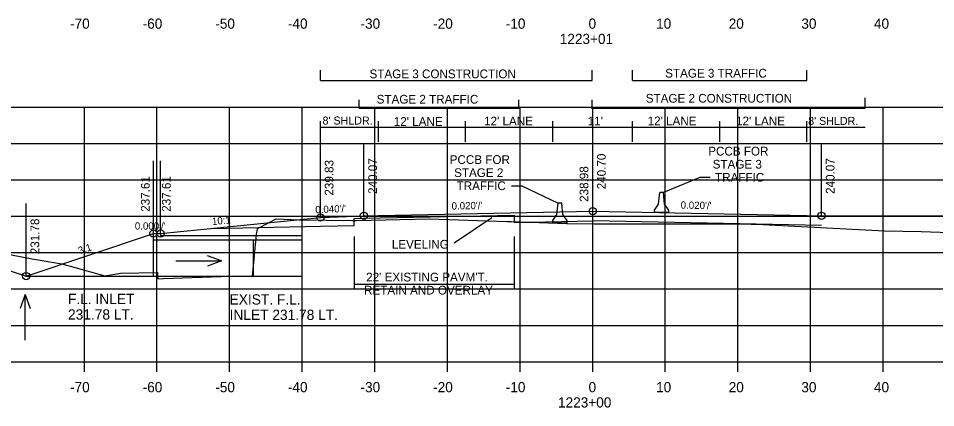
# Model space of a CAD drawing. Extents: x 1342547 to 1344156, y -1532351 to -1517216.
# Drawn here: x 1342623.8 to 1342750.1, y -1531484.1 to -1531430.6 of the extents above; entities that cross this region are included whole.
import ezdxf

# ---------------------------------------------------------------- set-up
doc = ezdxf.new("R2010")
doc.units = 0
for name, color, linetype in [('R_Alt Surface', 7, 'Continuous'), ('R_Axis', 7, 'Continuous'), ('R_Axis Annot', 7, 'Continuous'), ('R_Border Notes', 7, 'Continuous'), ('R_Draft', 7, 'Continuous'), ('R_Drive', 7, 'Continuous'), ('R_Exist Surface', 7, 'Continuous'), ('R_Fin Surface', 7, 'Continuous'), ('R_Grid', 7, 'Continuous'), ('R_MOT', 7, 'Continuous'), ('R_No Plot', 7, 'Continuous'), ('R_Water', 7, 'Continuous'), ('R_Xsect Elev', 7, 'Continuous'), ('R_Xsect Slope', 7, 'Continuous')]:
    doc.layers.add(name, color=color, linetype=linetype)

msp = doc.modelspace()

# ---------------------------------------------------------------- linework, layer by layer
at = {"layer": 'R_Alt Surface'}
for points in [[(1342670.04, -1531459.08), (1342670.04, -1531458.11), (1342671.37, -1531458.06), (1342692.04, -1531457.64)], [(1342692.04, -1531457.64), (1342692.04, -1531458.64), (1342702.87, -1531458.43)], [(1342734.37, -1531459.06), (1342702.87, -1531458.43)], [(1342650.37, -1531459.48), (1342665.37, -1531459.18)], [(1342665.37, -1531459.18), (1342670.04, -1531459.08)]]:
    msp.add_lwpolyline(points, dxfattribs=at)
at = {"layer": 'R_Axis'}
for p, q in [((1342562.87, -1531477.8), (1342842.87, -1531477.8)), ((1342632.87, -1531479.2), (1342632.87, -1531477.8)), ((1342642.87, -1531479.2), (1342642.87, -1531477.8)), ((1342652.87, -1531479.2), (1342652.87, -1531477.8)), ((1342662.87, -1531479.2), (1342662.87, -1531477.8)), ((1342672.87, -1531479.2), (1342672.87, -1531477.8)), ((1342682.87, -1531479.2), (1342682.87, -1531477.8)), ((1342692.87, -1531479.2), (1342692.87, -1531477.8)), ((1342702.87, -1531479.2), (1342702.87, -1531477.8)), ((1342712.87, -1531479.2), (1342712.87, -1531477.8)), ((1342722.87, -1531479.2), (1342722.87, -1531477.8)), ((1342732.87, -1531479.2), (1342732.87, -1531477.8)), ((1342742.87, -1531479.2), (1342742.87, -1531477.8))]:
    msp.add_line(p, q, dxfattribs=at)
at = {"layer": 'R_Draft'}
for p, q in [((1342665.37, -1531439.13), (1342665.37, -1531437.7)), ((1342702.78, -1531439.13), (1342702.78, -1531437.7)), ((1342708.37, -1531439.13), (1342708.37, -1531437.7)), ((1342732.37, -1531439.13), (1342732.37, -1531437.7)), ((1342665.37, -1531439.13), (1342702.78, -1531439.13)), ((1342708.37, -1531439.13), (1342732.37, -1531439.13)), ((1342670.72, -1531442.93), (1342670.72, -1531441.78)), ((1342692.72, -1531443.02), (1342692.72, -1531441.78)), ((1342702.78, -1531443.02), (1342702.78, -1531441.78)), ((1342740.38, -1531442.93), (1342740.38, -1531441.5)), ((1342670.72, -1531442.93), (1342692.72, -1531442.93)), ((1342702.78, -1531442.93), (1342740.38, -1531442.93)), ((1342670.04, -1531460.6), (1342670.04, -1531467.8)), ((1342692.04, -1531460.6), (1342692.04, -1531467.8)), ((1342670.04, -1531467.13), (1342692.04, -1531467.13))]:
    msp.add_line(p, q, dxfattribs=at)
for points in [[(1342717.62, -1531452.45), (1342712.61, -1531454.53)], [(1342719.06, -1531452.45), (1342717.62, -1531452.45)], [(1342691.67, -1531453.62), (1342693.11, -1531453.62)], [(1342693.11, -1531453.62), (1342698.11, -1531455.98)]]:
    msp.add_lwpolyline(points, dxfattribs=at)
at = {"layer": 'R_Drive'}
msp.add_lwpolyline([(1342734.37, -1531457.72), (1342752.37, -1531457.68), (1342842.87, -1531459.71)], dxfattribs=at)
at = {"layer": 'R_Exist Surface'}
msp.add_lwpolyline([(1342615.89, -1531461.76), (1342625.7, -1531463.65), (1342629.76, -1531464.35), (1342635.7, -1531465.98), (1342637.84, -1531465.62), (1342642.95, -1531465.53), (1342643, -1531466.39), (1342643.77, -1531466.37), (1342651.7, -1531466.07), (1342655.92, -1531465.97), (1342655.99, -1531465.98), (1342656.02, -1531465.98), (1342656.26, -1531463.7), (1342656.56, -1531460.23), (1342656.67, -1531459.86), (1342656.72, -1531459.5), (1342658.41, -1531458.62), (1342659.27, -1531458.14), (1342662.46, -1531458.28), (1342662.49, -1531458.28), (1342662.55, -1531458.28), (1342669.78, -1531458.37), (1342670.36, -1531458.36), (1342680.4, -1531458.17), (1342691.04, -1531458.51), (1342691.43, -1531458.52), (1342691.71, -1531458.53), (1342699.28, -1531458.78), (1342699.39, -1531458.78), (1342703.09, -1531458.82), (1342719.19, -1531458.85), (1342724.7, -1531458.87), (1342725.82, -1531458.9), (1342726.31, -1531458.94), (1342743.07, -1531459.79), (1342748.11, -1531459.91), (1342751.98, -1531460.03)], dxfattribs=at)
at = {"layer": 'R_Fin Surface'}
msp.add_lwpolyline([(1342605.9, -1531459.69), (1342624.86, -1531466.02), (1342642.37, -1531460.18), (1342643.37, -1531460.18), (1342665.37, -1531457.96), (1342671.37, -1531457.72), (1342673.37, -1531457.68), (1342702.87, -1531457.09), (1342732.37, -1531457.68), (1342734.37, -1531457.72)], dxfattribs=at)
at = {"layer": 'R_Grid'}
for p, q in [((1342562.87, -1531442.8), (1342842.87, -1531442.8)), ((1342632.87, -1531477.8), (1342632.87, -1531442.8)), ((1342642.87, -1531477.8), (1342642.87, -1531442.8)), ((1342652.87, -1531477.8), (1342652.87, -1531442.8)), ((1342662.87, -1531477.8), (1342662.87, -1531442.8)), ((1342672.87, -1531477.8), (1342672.87, -1531442.8)), ((1342682.87, -1531477.8), (1342682.87, -1531442.8)), ((1342692.87, -1531477.8), (1342692.87, -1531442.8)), ((1342702.87, -1531477.8), (1342702.87, -1531442.8)), ((1342712.87, -1531477.8), (1342712.87, -1531442.8)), ((1342722.87, -1531477.8), (1342722.87, -1531442.8)), ((1342732.87, -1531477.8), (1342732.87, -1531442.8)), ((1342742.87, -1531477.8), (1342742.87, -1531442.8)), ((1342562.87, -1531447.8), (1342842.87, -1531447.8)), ((1342562.87, -1531452.8), (1342842.87, -1531452.8)), ((1342562.87, -1531457.8), (1342842.87, -1531457.8)), ((1342562.87, -1531462.8), (1342842.87, -1531462.8)), ((1342562.87, -1531467.8), (1342842.87, -1531467.8)), ((1342562.87, -1531472.8), (1342842.87, -1531472.8)), ((1342562.87, -1531477.8), (1342842.87, -1531477.8))]:
    msp.add_line(p, q, dxfattribs=at)
at = {"layer": 'R_MOT'}
for p, q in [((1342711.95, -1531456.12), (1342712.11, -1531454.53)), ((1342712.36, -1531454.53), (1342712.11, -1531454.53)), ((1342712.61, -1531454.53), (1342712.36, -1531454.53)), ((1342712.78, -1531456.12), (1342712.61, -1531454.53)), ((1342697.95, -1531457.56), (1342698.11, -1531455.98)), ((1342698.36, -1531455.98), (1342698.11, -1531455.98)), ((1342698.61, -1531455.98), (1342698.36, -1531455.98)), ((1342698.78, -1531457.56), (1342698.61, -1531455.98)), ((1342711.36, -1531457.28), (1342711.37, -1531456.95)), ((1342711.37, -1531456.95), (1342711.95, -1531456.12)), ((1342713.37, -1531456.95), (1342712.78, -1531456.12)), ((1342713.37, -1531457.28), (1342713.37, -1531456.95)), ((1342697.37, -1531458.39), (1342697.95, -1531457.56)), ((1342697.37, -1531458.73), (1342697.37, -1531458.39)), ((1342699.37, -1531458.39), (1342698.78, -1531457.56)), ((1342699.37, -1531458.73), (1342699.37, -1531458.39)), ((1342713.37, -1531457.28), (1342711.36, -1531457.28)), ((1342699.37, -1531458.73), (1342697.37, -1531458.73))]:
    msp.add_line(p, q, dxfattribs=at)
at = {"layer": 'R_No Plot'}
for centre in [(1342702.87, -1531457.09), (1342702.87, -1531457.09), (1342665.37, -1531457.96), (1342665.37, -1531457.96), (1342671.37, -1531457.72), (1342671.37, -1531457.72), (1342734.37, -1531457.72), (1342734.37, -1531457.72), (1342642.37, -1531460.18), (1342643.37, -1531460.18), (1342624.86, -1531466.02), (1342624.86, -1531466.02)]:
    msp.add_circle(centre, 0.5, dxfattribs=at)
at = {"layer": 'R_Water'}
for p, q in [((1342642.37, -1531466.02), (1342642.37, -1531460.18)), ((1342643.37, -1531460.43), (1342652.87, -1531460.43)), ((1342652.87, -1531460.43), (1342656.14, -1531460.43)), ((1342656.14, -1531460.43), (1342662.87, -1531460.43)), ((1342643.37, -1531461.02), (1342652.87, -1531461.02)), ((1342652.87, -1531461.02), (1342656.14, -1531461.02)), ((1342656.14, -1531466.02), (1342656.14, -1531461.02)), ((1342656.14, -1531461.02), (1342662.87, -1531461.02)), ((1342651.74, -1531463.94), (1342649.82, -1531463.24)), ((1342645.46, -1531463.94), (1342651.74, -1531463.94)), ((1342651.74, -1531463.94), (1342649.82, -1531464.64)), ((1342643.37, -1531466.02), (1342652.87, -1531466.02)), ((1342652.87, -1531466.02), (1342656.14, -1531466.02)), ((1342656.14, -1531466.02), (1342662.87, -1531466.02)), ((1342624.73, -1531468.57), (1342624.03, -1531470.49)), ((1342624.73, -1531474.85), (1342624.73, -1531468.57)), ((1342624.73, -1531468.57), (1342625.43, -1531470.49))]:
    msp.add_line(p, q, dxfattribs=at)
for points in [[(1342642.37, -1531460.18), (1342643.37, -1531460.18), (1342643.37, -1531460.43)], [(1342642.37, -1531461.02), (1342643.37, -1531461.02)], [(1342624.86, -1531466.02), (1342643.37, -1531466.02)]]:
    msp.add_lwpolyline(points, dxfattribs=at)
at = {"layer": 'R_Xsect Elev'}
for p, q in [((1342665.37, -1531457.96), (1342665.37, -1531444.71)), ((1342740.37, -1531445.57), (1342665.37, -1531445.57)), ((1342673.37, -1531447.57), (1342673.37, -1531444.71)), ((1342685.37, -1531447.57), (1342685.37, -1531444.71)), ((1342697.37, -1531447.57), (1342697.37, -1531444.71)), ((1342708.37, -1531447.57), (1342708.37, -1531444.71)), ((1342720.37, -1531447.57), (1342720.37, -1531444.71)), ((1342732.37, -1531447.57), (1342732.37, -1531444.71)), ((1342702.87, -1531457.09), (1342702.87, -1531447.09)), ((1342665.37, -1531457.96), (1342665.37, -1531447.96)), ((1342665.37, -1531457.96), (1342665.37, -1531447.96)), ((1342671.37, -1531457.72), (1342671.37, -1531447.72)), ((1342734.37, -1531457.72), (1342734.37, -1531447.72)), ((1342702.87, -1531458.82), (1342702.87, -1531448.82)), ((1342642.37, -1531460.18), (1342642.37, -1531450.18)), ((1342643.37, -1531460.18), (1342643.37, -1531450.18)), ((1342624.86, -1531466.02), (1342624.86, -1531456.02)), ((1342689, -1531458), (1342683.81, -1531461.49))]:
    msp.add_line(p, q, dxfattribs=at)

# ---------------------------------------------------------------- texts
at = {"layer": 'R_Axis Annot'}
for s, p in [('-70', (1342630.9, -1531432)), ('-60', (1342640.9, -1531432)), ('-50', (1342650.9, -1531432)), ('-40', (1342660.9, -1531432)), ('-30', (1342670.9, -1531432)), ('-20', (1342680.9, -1531432)), ('-10', (1342690.9, -1531432)), ('0', (1342702.3, -1531432)), ('10', (1342711.6, -1531432)), ('20', (1342721.6, -1531432)), ('30', (1342731.6, -1531432)), ('40', (1342741.6, -1531432)), ('1223+01', (1342698.34, -1531434.1)), ('-70', (1342630.9, -1531482)), ('-60', (1342640.9, -1531482)), ('-50', (1342650.9, -1531482)), ('-40', (1342660.9, -1531482)), ('-30', (1342670.9, -1531482)), ('-20', (1342680.9, -1531482)), ('-10', (1342690.9, -1531482)), ('0', (1342702.3, -1531482)), ('10', (1342711.6, -1531482)), ('20', (1342721.6, -1531482)), ('30', (1342731.6, -1531482)), ('40', (1342741.6, -1531482)), ('1223+00', (1342698.1, -1531484.1))]:
    msp.add_text(s, height=1.4, dxfattribs=at).set_placement(p)
at = {"layer": 'R_Border Notes'}
for s, height, p in [('F.L. INLET', 1.415, (1342630.62, -1531469.88)), ('F.L. INLET', 1.415, (1342630.62, -1531469.88)), ('EXIST. F.L.', 1.4147, (1342652.87, -1531469.94)), ('EXIST. F.L.', 1.4147, (1342652.87, -1531469.94)), ('231.78 LT.', 1.415, (1342630.62, -1531472.01)), ('231.78 LT.', 1.415, (1342630.62, -1531472.01)), ('INLET 231.78 LT.', 1.4147, (1342652.87, -1531472.06)), ('INLET 231.78 LT.', 1.4147, (1342652.87, -1531472.06))]:
    msp.add_text(s, height=height, dxfattribs=at).set_placement(p)
at = {"layer": 'R_Draft'}
for s, p in [('STAGE 3 CONSTRUCTION', (1342672.14, -1531438.81)), ('STAGE 3 TRAFFIC', (1342712.85, -1531438.72)), ('STAGE 2 TRAFFIC', (1342673.12, -1531442.3)), ('STAGE 2 CONSTRUCTION', (1342710.18, -1531442.17)), ('PCCB FOR', (1342718.78, -1531449.44)), ('PCCB FOR', (1342683.18, -1531450.6)), ('STAGE 3', (1342719.39, -1531451.24)), ('STAGE 2', (1342683.79, -1531452.4)), ('TRAFFIC', (1342719.72, -1531453.04)), ('TRAFFIC', (1342684.13, -1531454.2)), ("22' EXISTING PAVM'T.", (1342671.68, -1531466.76)), ('RETAIN AND OVERLAY', (1342671.39, -1531468.56))]:
    msp.add_text(s, height=1.2, dxfattribs=at).set_placement(p)
at = {"layer": 'R_Xsect Elev'}
for s, height, p in [("8' SHLDR.", 1.1, (1342665.67, -1531445.18)), ("12' LANE", 1.2, (1342675.48, -1531445.36)), ("12' LANE", 1.2, (1342687.91, -1531445.3)), ("11'", 1.2, (1342702.18, -1531445.3)), ("12' LANE", 1.2, (1342710.44, -1531445.28)), ("12' LANE", 1.2, (1342722.61, -1531445.29)), ("8' SHLDR.", 1.1, (1342732.54, -1531445.23)), ('LEVELING', 1.2, (1342675.21, -1531462.25))]:
    msp.add_text(s, height=height, dxfattribs=at).set_placement(p)
for s, p in [('240.70', (1342704.67, -1531454.09)), ('239.83', (1342667.17, -1531454.96)), ('240.07', (1342673.17, -1531454.72)), ('240.07', (1342736.17, -1531454.72)), ('238.98', (1342702.27, -1531455.82)), ('237.61', (1342641.87, -1531457.18)), ('237.61', (1342644.76, -1531457.18)), ('231.78', (1342626.66, -1531463.02))]:
    msp.add_text(s, height=1.2, rotation=90, dxfattribs=at).set_placement(p)
at = {"layer": 'R_Xsect Slope'}
for s, rotation, p in [("0.020'/'", 1.1458, (1342683.45, -1531456.88)), ("0.020'/'", 358.8542, (1342714.98, -1531456.74)), ("0.040'/'", 2.2906, (1342664.69, -1531457.39)), ('10:1', 5.58, (1342650.49, -1531459.02)), ("0.000'/'", 359.9313, (1342639.82, -1531459.63)), ('3:1', 18.4349, (1342632.21, -1531463.04))]:
    msp.add_text(s, height=1, rotation=rotation, dxfattribs=at).set_placement(p)

doc.saveas('drawing.dxf')
